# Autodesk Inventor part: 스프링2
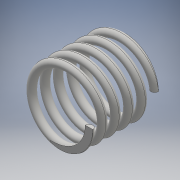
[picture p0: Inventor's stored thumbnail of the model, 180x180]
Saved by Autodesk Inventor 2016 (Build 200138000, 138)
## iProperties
Created: 2019-11
Part Number: 스프링2
Material: 일반
Document SubType Name: Modeling
Designer: user
Density: 1 g/cm^3
Appearance: 기본값
Mass: 0.818655 g
Surface Area: 16.7049 cm^2
Volume: 0.818655 cm^3
Author: user
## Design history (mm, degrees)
sketch "스케치1"
  geometry: L1 (0, 0)-(8.5, 0); L2 (8.5, 0)-(8.5, 17.5); L3 (8.5, 17.5)-(0, 17.5); L4 (0, 17.5)-(0, 0); C1 r 1 at (8.5, 0)
  constraints: 8 end point, 2 parallel, 1 centre point, 1 coincident, 1 horizontal, 1 perpendicular
  dimensions: "d0" = 17 diameter of L2 L4; "d1" = 2 diameter of C1; "d2" = 17.5 distance of L1.end L2.end (derived)
feature "코일1" sketch "스케치1" pitch "d3" = 10; turns "d5" = 5; dims "d4" = 17.5 (= d2), "d6" = 0, angle "d7" = 90 deg, angle "d8" = 90 deg, "d9" = 0, "d10" = 0
sketch "스케치2"
  geometry: L1 (-15.597, 17.5)-(15.597, 17.5); L2 (15.597, 17.5)-(15.597, 0); L3 (15.597, 0)-(-15.597, 0); L4 (-15.597, 0)-(-15.597, 17.5); 2 further points
  constraints: 8 end point, 2 parallel, 1 coincident, 1 horizontal, 1 midpoint, 1 perpendicular
  dimensions: "d11" = 17.5 distance of L1.end L2.end (= d2)
extrude "돌출1" sketch "스케치2" stored distance "d12" = 50; taper "d13" = 0 deg
node "솔리드1"
